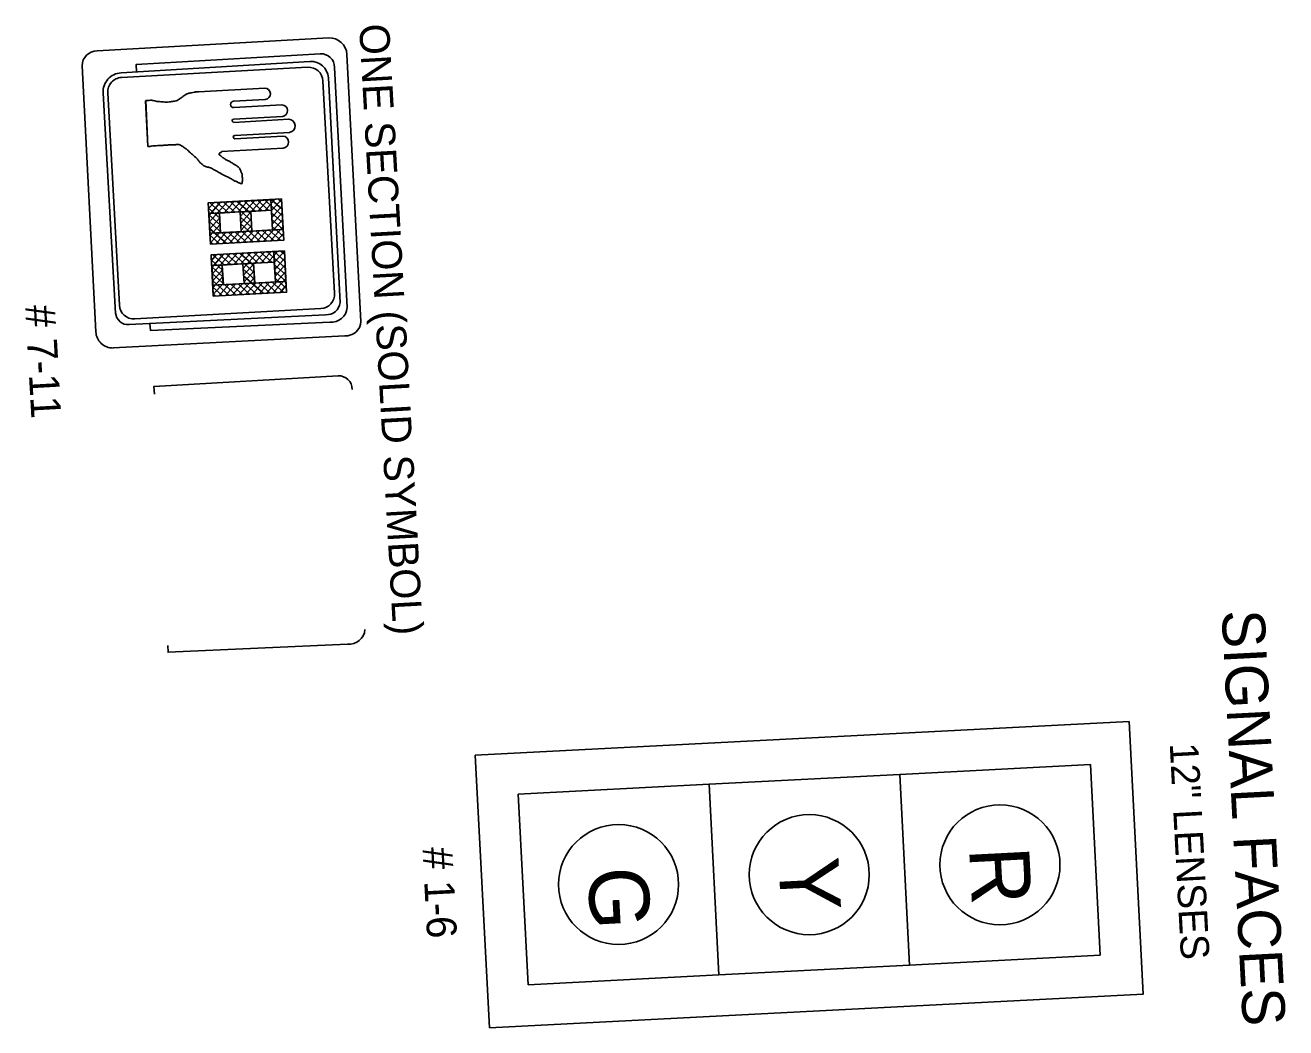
# Model space of a CAD drawing. Extents: x -218554 to 420114, y -565956 to -483460.
# Drawn here: x -218553.8 to -218475.3, y -483522.4 to -483459.9 of the extents above; entities that cross this region are included whole.
import ezdxf

# ---------------------------------------------------------------- set-up
doc = ezdxf.new("R2010")
doc.units = 0
for name, color, linetype in [('C-ANNO-TEXT', 7, 'Continuous'), ('Level 1', 7, 'Continuous'), ('Level 61', 7, 'Continuous')]:
    doc.layers.add(name, color=color, linetype=linetype)

msp = doc.modelspace()

# ---------------------------------------------------------------- linework, layer by layer
at = {"layer": 'Level 1'}
for p, q in [((-218534.899, -483460.726), (-218549.338, -483461.533)), ((-218532.891, -483478.4), (-218533.762, -483461.757)), ((-218550.267, -483462.458), (-218549.412, -483479.034)), ((-218536.07, -483462.195), (-218547.834, -483462.901)), ((-218533.745, -483477.527), (-218534.536, -483462.56)), ((-218534.19, -483477.206), (-218534.915, -483463.203)), ((-218548.965, -483464.164), (-218548.185, -483477.873)), ((-218543.022, -483464.078), (-218538.886, -483463.85)), ((-218538.886, -483463.85), (-218543.022, -483464.078)), ((-218546.164, -483467.478), (-218546.32, -483464.647)), ((-218546.305, -483464.631), (-218546.165, -483467.49)), ((-218538.855, -483464.56), (-218540.827, -483464.668)), ((-218540.827, -483464.668), (-218538.855, -483464.56)), ((-218540.805, -483465.068), (-218537.813, -483464.903)), ((-218537.813, -483464.903), (-218540.805, -483465.068)), ((-218540.82, -483465.986), (-218537.395, -483465.797)), ((-218537.395, -483465.797), (-218540.82, -483465.986)), ((-218537.782, -483465.614), (-218540.816, -483465.781)), ((-218540.816, -483465.781), (-218537.782, -483465.614)), ((-218537.342, -483466.612), (-218540.743, -483466.799)), ((-218540.743, -483466.799), (-218537.342, -483466.612)), ((-218546.167, -483467.492), (-218546.164, -483467.478)), ((-218540.748, -483467.004), (-218537.763, -483466.84)), ((-218537.763, -483466.84), (-218540.748, -483467.004)), ((-218537.746, -483467.601), (-218541.588, -483467.812)), ((-218541.588, -483467.812), (-218537.746, -483467.601)), ((-218542.396, -483471.323), (-218541.693, -483471.952)), ((-218542.062, -483470.991), (-218542.393, -483471.361)), ((-218541.637, -483470.968), (-218542.37, -483471.786)), ((-218541.213, -483470.944), (-218542.347, -483472.21)), ((-218542.3, -483471.004), (-218541.598, -483471.633)), ((-218541.876, -483470.981), (-218541.174, -483471.61)), ((-218541.451, -483470.957), (-218540.749, -483471.586)), ((-218540.788, -483470.921), (-218541.417, -483471.623)), ((-218541.027, -483470.934), (-218539.727, -483472.098)), ((-218540.364, -483470.898), (-218540.993, -483471.6)), ((-218540.602, -483470.911), (-218539.75, -483471.674)), ((-218539.939, -483470.874), (-218540.568, -483471.576)), ((-218539.514, -483470.851), (-218540.408, -483471.848)), ((-218539.09, -483470.827), (-218540.385, -483472.273)), ((-218540.178, -483470.887), (-218539.475, -483471.516)), ((-218539.753, -483470.864), (-218539.051, -483471.493)), ((-218539.328, -483470.841), (-218538.626, -483471.47)), ((-218538.665, -483470.804), (-218539.294, -483471.506)), ((-218538.904, -483470.817), (-218537.783, -483471.821)), ((-218538.241, -483470.781), (-218538.87, -483471.483)), ((-218538.479, -483470.794), (-218537.807, -483471.396)), ((-218537.84, -483470.784), (-218538.469, -483471.487)), ((-218537.817, -483471.209), (-218538.446, -483471.911)), ((-218538.055, -483470.77), (-218537.83, -483470.972)), ((-218542.372, -483471.747), (-218541.67, -483472.376)), ((-218542.349, -483472.172), (-218540.872, -483473.495)), ((-218541.694, -483471.933), (-218542.323, -483472.635)), ((-218540.423, -483471.569), (-218540.356, -483472.798)), ((-218540.406, -483471.894), (-218539.703, -483472.523)), ((-218539.732, -483471.995), (-218540.361, -483472.698)), ((-218539.758, -483471.532), (-218539.69, -483472.762)), ((-218537.77, -483472.058), (-218538.963, -483473.389)), ((-218538.462, -483471.616), (-218537.76, -483472.245)), ((-218538.439, -483472.041), (-218537.737, -483472.67)), ((-218537.794, -483471.633), (-218538.423, -483472.336)), ((-218542.325, -483472.596), (-218541.296, -483473.518)), ((-218541.671, -483472.357), (-218542.3, -483473.059)), ((-218541.647, -483472.782), (-218542.276, -483473.484)), ((-218541.306, -483472.851), (-218541.935, -483473.553)), ((-218540.881, -483472.827), (-218541.51, -483473.53)), ((-218541.15, -483472.842), (-218540.447, -483473.471)), ((-218540.457, -483472.804), (-218541.086, -483473.506)), ((-218540.725, -483472.819), (-218540.023, -483473.448)), ((-218539.709, -483472.42), (-218540.661, -483473.483)), ((-218540.382, -483472.319), (-218539.174, -483473.401)), ((-218540.359, -483472.743), (-218539.598, -483473.424)), ((-218539.607, -483472.757), (-218540.236, -483473.46)), ((-218539.183, -483472.734), (-218539.812, -483473.436)), ((-218539.451, -483472.749), (-218538.749, -483473.378)), ((-218538.758, -483472.711), (-218539.387, -483473.413)), ((-218539.027, -483472.725), (-218538.324, -483473.354)), ((-218538.602, -483472.702), (-218537.9, -483473.331)), ((-218537.747, -483472.483), (-218538.538, -483473.366)), ((-218538.416, -483472.465), (-218537.713, -483473.094)), ((-218537.724, -483472.907), (-218538.114, -483473.343)), ((-218542.302, -483473.021), (-218541.721, -483473.541)), ((-218542.279, -483473.445), (-218542.145, -483473.565)), ((-218541.884, -483474.228), (-218542.215, -483474.599)), ((-218541.459, -483474.205), (-218542.192, -483475.023)), ((-218541.034, -483474.182), (-218542.168, -483475.448)), ((-218542.122, -483474.242), (-218541.42, -483474.871)), ((-218541.698, -483474.218), (-218540.995, -483474.847)), ((-218541.273, -483474.195), (-218540.571, -483474.824)), ((-218540.61, -483474.158), (-218541.239, -483474.861)), ((-218540.848, -483474.171), (-218539.548, -483475.336)), ((-218540.185, -483474.135), (-218540.814, -483474.837)), ((-218540.424, -483474.148), (-218539.572, -483474.911)), ((-218539.761, -483474.111), (-218540.39, -483474.814)), ((-218539.336, -483474.088), (-218540.23, -483475.086)), ((-218538.912, -483474.065), (-218540.206, -483475.51)), ((-218539.999, -483474.125), (-218539.297, -483474.754)), ((-218539.575, -483474.101), (-218538.872, -483474.73)), ((-218539.15, -483474.078), (-218538.448, -483474.707)), ((-218538.487, -483474.041), (-218539.116, -483474.744)), ((-218538.726, -483474.054), (-218537.605, -483475.058)), ((-218538.063, -483474.018), (-218538.692, -483474.72)), ((-218538.301, -483474.031), (-218537.628, -483474.633)), ((-218537.662, -483474.022), (-218538.291, -483474.724)), ((-218537.639, -483474.446), (-218538.268, -483475.148)), ((-218537.876, -483474.008), (-218537.652, -483474.209)), ((-218542.217, -483474.56), (-218541.515, -483475.189)), ((-218542.194, -483474.985), (-218541.492, -483475.614)), ((-218541.516, -483475.17), (-218542.145, -483475.872)), ((-218540.245, -483474.806), (-218540.177, -483476.036)), ((-218540.227, -483475.131), (-218539.525, -483475.76)), ((-218539.554, -483475.233), (-218540.183, -483475.935)), ((-218539.58, -483474.769), (-218539.512, -483475.999)), ((-218537.592, -483475.295), (-218538.784, -483476.627)), ((-218538.284, -483474.854), (-218537.582, -483475.483)), ((-218538.261, -483475.278), (-218537.558, -483475.907)), ((-218537.615, -483474.871), (-218538.244, -483475.573)), ((-218542.17, -483475.409), (-218540.693, -483476.732)), ((-218542.147, -483475.834), (-218541.118, -483476.755)), ((-218541.493, -483475.594), (-218542.122, -483476.297)), ((-218541.469, -483476.019), (-218542.098, -483476.721)), ((-218541.127, -483476.088), (-218541.756, -483476.79)), ((-218540.703, -483476.065), (-218541.332, -483476.767)), ((-218540.971, -483476.079), (-218540.269, -483476.708)), ((-218540.278, -483476.041), (-218540.907, -483476.744)), ((-218540.547, -483476.056), (-218539.844, -483476.685)), ((-218539.531, -483475.657), (-218540.483, -483476.72)), ((-218540.204, -483475.556), (-218538.995, -483476.638)), ((-218540.18, -483475.98), (-218539.42, -483476.662)), ((-218539.429, -483475.995), (-218540.058, -483476.697)), ((-218539.005, -483475.971), (-218539.634, -483476.673)), ((-218539.273, -483475.986), (-218538.571, -483476.615)), ((-218538.58, -483475.948), (-218539.209, -483476.65)), ((-218538.848, -483475.963), (-218538.146, -483476.592)), ((-218538.424, -483475.939), (-218537.722, -483476.568)), ((-218537.569, -483475.72), (-218538.36, -483476.603)), ((-218538.237, -483475.703), (-218537.535, -483476.332)), ((-218542.124, -483476.258), (-218541.543, -483476.779)), ((-218542.1, -483476.683), (-218541.967, -483476.802)), ((-218537.545, -483476.144), (-218537.935, -483476.58)), ((-218547.327, -483478.585), (-218535.092, -483477.969)), ((-218548.331, -483480.045), (-218533.902, -483479.285))]:
    msp.add_line(p, q, dxfattribs=at)
for points in [[(-218535.423, -483461.711), (-218546.895, -483462.377), (-218546.869, -483462.859)], [(-218536.215, -483462.551), (-218547.818, -483463.19)], [(-218534.529, -483476.634), (-218535.257, -483463.409)], [(-218548.676, -483464.148), (-218547.948, -483477.373)], [(-218540.356, -483472.798), (-218541.643, -483472.869), (-218541.71, -483471.639), (-218540.423, -483471.569)], [(-218539.69, -483472.762), (-218538.403, -483472.691), (-218538.471, -483471.461), (-218539.758, -483471.532)], [(-218540.177, -483476.036), (-218541.464, -483476.107), (-218541.532, -483474.877), (-218540.245, -483474.806)], [(-218539.512, -483475.999), (-218538.225, -483475.928), (-218538.293, -483474.698), (-218539.58, -483474.769)], [(-218546.99, -483478.23), (-218535.386, -483477.591)], [(-218546.04, -483478.511), (-218546.016, -483478.945), (-218534.836, -483478.439)], [(-218534.319, -483481.772), (-218545.79, -483482.438), (-218545.764, -483482.92)], [(-218544.936, -483498.572), (-218544.911, -483499.006), (-218533.731, -483498.5)]]:
    msp.add_lwpolyline(points, dxfattribs=at)
for points in [[(-218537.842, -483470.759), (-218537.701, -483473.32), (-218542.272, -483473.572), (-218542.413, -483471.01)], [(-218542.413, -483471.01), (-218542.378, -483471.666), (-218538.471, -483471.461), (-218538.505, -483470.806)], [(-218537.842, -483470.759), (-218537.742, -483472.656), (-218538.403, -483472.691), (-218538.502, -483470.793)], [(-218541.71, -483471.639), (-218541.646, -483472.861), (-218542.307, -483472.895), (-218542.371, -483471.674)], [(-218539.758, -483471.532), (-218539.693, -483472.764), (-218540.356, -483472.798), (-218540.42, -483471.567)], [(-218537.742, -483472.656), (-218537.707, -483473.333), (-218542.272, -483473.572), (-218542.307, -483472.895)], [(-218537.664, -483473.996), (-218537.523, -483476.557), (-218542.093, -483476.809), (-218542.234, -483474.248)], [(-218542.234, -483474.248), (-218542.2, -483474.903), (-218538.293, -483474.698), (-218538.327, -483474.043)], [(-218537.664, -483473.996), (-218537.564, -483475.894), (-218538.225, -483475.928), (-218538.324, -483474.031)], [(-218541.532, -483474.877), (-218541.468, -483476.098), (-218542.129, -483476.133), (-218542.193, -483474.911)], [(-218539.58, -483474.769), (-218539.515, -483476.001), (-218540.177, -483476.036), (-218540.242, -483474.804)], [(-218537.564, -483475.894), (-218537.529, -483476.57), (-218542.093, -483476.809), (-218542.129, -483476.133)]]:
    msp.add_lwpolyline(points, close=True, dxfattribs=at)
for centre, radius, start, end in [((-218534.847, -483461.81), 1.086, 2.77432, 92.77432), ((-218549.339, -483462.46), 0.927, 89.93321, 179.93321), ((-218535.404, -483462.579), 0.869, 1.27514, 91.27514), ((-218536.165, -483463.459), 0.909, 3.15216, 93.15216), ((-218535.996, -483463.276), 1.083, 3.88192, 93.88192), ((-218547.768, -483464.098), 1.198, 93.15216, 183.15216), ((-218547.768, -483464.098), 0.909, 93.15216, 183.15216), ((-218538.891, -483464.205), 0.356, 275.81971, 89.16653), ((-218538.891, -483464.205), 0.356, 275.81971, 89.16653), ((-218540.817, -483464.868), 0.2, 93.15216, 273.15216), ((-218540.817, -483464.868), 0.2, 93.15216, 273.15216), ((-218537.818, -483465.259), 0.356, 275.81971, 89.16653), ((-218537.818, -483465.259), 0.356, 275.81971, 89.16653), ((-218540.818, -483465.883), 0.102, 88.57477, 268.57477), ((-218540.818, -483465.883), 0.102, 88.57477, 268.57477), ((-218537.392, -483466.206), 0.409, 277.05213, 90.39894), ((-218537.392, -483466.206), 0.409, 277.05213, 90.39894), ((-218540.745, -483466.9), 0.104, 88.04746, 268.04746), ((-218540.745, -483466.9), 0.104, 88.04746, 268.04746), ((-218537.777, -483467.221), 0.381, 274.62974, 87.97656), ((-218537.777, -483467.221), 0.381, 274.62974, 87.97656), ((-218535.437, -483476.684), 0.909, 273.15216, 3.15216), ((-218547.04, -483477.323), 0.909, 183.15216, 273.15216), ((-218535.023, -483477.136), 0.836, 265.22621, 355.22621), ((-218534.747, -483477.437), 1.005, 264.91062, 354.91062), ((-218547.4, -483477.8), 0.788, 185.26181, 275.26181), ((-218533.839, -483478.337), 0.95, 266.18024, 356.18024), ((-218548.365, -483478.999), 1.047, 181.91264, 271.91264), ((-218534.3, -483482.64), 0.869, 1.27514, 91.27514), ((-218533.642, -483497.498), 1.005, 264.91062, 354.91062)]:
    msp.add_arc(centre, radius, start, end, dxfattribs=at)
for points in [[(-218546.305, -483464.631), (-218546.148, -483464.622), (-218545.882, -483464.618), (-218545.603, -483464.681), (-218545.287, -483464.703), (-218545.109, -483464.723), (-218544.765, -483464.704), (-218544.482, -483464.659), (-218544.337, -483464.621), (-218544.099, -483464.46), (-218543.862, -483464.29), (-218543.661, -483464.19), (-218543.447, -483464.139), (-218543.282, -483464.101), (-218543.175, -483464.095), (-218543.022, -483464.078)], [(-218543.022, -483464.078), (-218543.175, -483464.095), (-218543.282, -483464.101), (-218543.447, -483464.139), (-218543.661, -483464.19), (-218543.862, -483464.29), (-218544.099, -483464.46), (-218544.337, -483464.621), (-218544.482, -483464.659), (-218544.765, -483464.704), (-218545.109, -483464.723), (-218545.287, -483464.703), (-218545.603, -483464.681), (-218545.882, -483464.618), (-218546.148, -483464.622), (-218546.305, -483464.631)], [(-218541.587, -483467.81), (-218541.591, -483467.838), (-218541.668, -483467.882), (-218541.725, -483467.934), (-218541.732, -483467.964), (-218541.721, -483468.013), (-218541.679, -483468.04), (-218541.576, -483468.123), (-218541.494, -483468.187), (-218541.433, -483468.223), (-218541.382, -483468.26), (-218541.29, -483468.324), (-218541.209, -483468.358), (-218541.098, -483468.412), (-218541.037, -483468.447), (-218540.925, -483468.51), (-218540.822, -483468.583), (-218540.721, -483468.637), (-218540.619, -483468.7), (-218540.547, -483468.755), (-218540.464, -483468.839), (-218540.418, -483468.945), (-218540.385, -483469.002), (-218540.352, -483469.089), (-218540.318, -483469.165), (-218540.291, -483469.283), (-218540.286, -483469.381), (-218540.279, -483469.508), (-218540.283, -483469.626), (-218540.294, -483469.764), (-218540.312, -483469.805), (-218540.34, -483469.816), (-218540.471, -483469.764), (-218540.542, -483469.729), (-218540.614, -483469.694), (-218540.694, -483469.659), (-218540.744, -483469.642), (-218540.876, -483469.57), (-218541.06, -483469.462), (-218541.353, -483469.32), (-218541.687, -483469.142), (-218541.922, -483468.998), (-218542.074, -483468.917), (-218542.215, -483468.846), (-218542.328, -483468.808), (-218542.385, -483468.787), (-218542.627, -483468.713), (-218542.801, -483468.584), (-218542.925, -483468.483), (-218543.051, -483468.332), (-218543.126, -483468.238), (-218543.395, -483467.997), (-218543.622, -483467.783), (-218543.778, -483467.644), (-218543.951, -483467.526), (-218544.028, -483467.467), (-218544.136, -483467.418), (-218544.236, -483467.365), (-218544.453, -483467.377), (-218544.647, -483467.377), (-218544.824, -483467.387), (-218545.059, -483467.41), (-218545.285, -483467.423), (-218545.648, -483467.443), (-218545.941, -483467.468), (-218546.048, -483467.483), (-218546.127, -483467.488), (-218546.165, -483467.49)], [(-218546.165, -483467.49), (-218546.127, -483467.488), (-218546.048, -483467.483), (-218545.941, -483467.468), (-218545.648, -483467.443), (-218545.285, -483467.423), (-218545.059, -483467.41), (-218544.824, -483467.387), (-218544.647, -483467.377), (-218544.453, -483467.377), (-218544.236, -483467.365), (-218544.136, -483467.418), (-218544.028, -483467.467), (-218543.951, -483467.526), (-218543.778, -483467.644), (-218543.622, -483467.783), (-218543.395, -483467.997), (-218543.126, -483468.238), (-218543.051, -483468.332), (-218542.925, -483468.483), (-218542.801, -483468.584), (-218542.627, -483468.713), (-218542.385, -483468.787), (-218542.328, -483468.808), (-218542.215, -483468.846), (-218542.074, -483468.917), (-218541.922, -483468.998), (-218541.687, -483469.142), (-218541.353, -483469.32), (-218541.06, -483469.462), (-218540.876, -483469.57), (-218540.744, -483469.642), (-218540.694, -483469.659), (-218540.614, -483469.694), (-218540.542, -483469.729), (-218540.471, -483469.764), (-218540.34, -483469.816), (-218540.312, -483469.805), (-218540.294, -483469.764), (-218540.283, -483469.626), (-218540.279, -483469.508), (-218540.286, -483469.381), (-218540.291, -483469.283), (-218540.318, -483469.165), (-218540.352, -483469.089), (-218540.385, -483469.002), (-218540.418, -483468.945), (-218540.464, -483468.839), (-218540.547, -483468.755), (-218540.619, -483468.7), (-218540.721, -483468.637), (-218540.822, -483468.583), (-218540.925, -483468.51), (-218541.037, -483468.447), (-218541.098, -483468.412), (-218541.209, -483468.358), (-218541.29, -483468.324), (-218541.382, -483468.26), (-218541.433, -483468.223), (-218541.494, -483468.187), (-218541.576, -483468.123), (-218541.679, -483468.04), (-218541.721, -483468.013), (-218541.732, -483467.964), (-218541.725, -483467.934), (-218541.668, -483467.882), (-218541.591, -483467.838), (-218541.587, -483467.81)]]:
    msp.add_spline(points, degree=3, dxfattribs=at)
at = {"layer": 'Level 61'}
for p, q in [((-218499.314, -483506.609), (-218511.199, -483507.222)), ((-218487.429, -483505.996), (-218499.314, -483506.609)), ((-218499.314, -483506.609), (-218498.701, -483518.494)), ((-218487.429, -483505.996), (-218486.816, -483517.88)), ((-218511.199, -483507.222), (-218523.084, -483507.835)), ((-218511.199, -483507.222), (-218510.586, -483519.107)), ((-218523.084, -483507.835), (-218522.471, -483519.72)), ((-218498.701, -483518.494), (-218510.586, -483519.107)), ((-218486.816, -483517.88), (-218498.701, -483518.494)), ((-218510.586, -483519.107), (-218522.471, -483519.72))]:
    msp.add_line(p, q, dxfattribs=at)
msp.add_lwpolyline([(-218524.886, -483522.398), (-218484.138, -483520.296), (-218485.014, -483503.317), (-218525.762, -483505.42)], close=True, dxfattribs=at)
for centre in [(-218493.065, -483512.245), (-218516.835, -483513.471), (-218504.95, -483512.858)]:
    msp.add_circle(centre, 3.74, dxfattribs=at)

# ---------------------------------------------------------------- texts
at = {"layer": 'C-ANNO-TEXT'}
for s, height, rotation, p in [('ONE SECTION (SOLID SYMBOL)', 1.86667, 273.19877, (-218533.006, -483459.894)), ('# 7-11', 1.8667, 273.19877, (-218553.823, -483477.414)), ('# 1-6', 1.8667, 272.95326, (-218529.057, -483511.186))]:
    msp.add_text(s, height=height, rotation=rotation, dxfattribs=at).set_placement(p)
at = {"layer": 'Level 61'}
for s, height, rotation, p in [('SIGNAL FACES', 2.66667, 272.95326, (-218479.253, -483496.418)), ('12" LENSES', 1.7778, 273.02529, (-218482.488, -483504.688)), ('R', 3.739, 272.95326, (-218494.991, -483511.211)), ('Y', 3.739, 272.95326, (-218506.873, -483511.868)), ('G', 3.739, 272.95326, (-218518.759, -483512.47))]:
    msp.add_text(s, height=height, rotation=rotation, dxfattribs=at).set_placement(p)

doc.saveas('drawing.dxf')
